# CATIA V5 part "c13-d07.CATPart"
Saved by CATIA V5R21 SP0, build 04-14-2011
Part number: Part1
Bounding box of the stored display mesh (mm): x -49.812 to 35, y -44.222 to 44.222, z 0 to 30
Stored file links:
  D:\CATIA V5R21 E-RESOURCES\CATIA-V5R21\catia-v5r21-Prts\c13_catia_v5r21_prt\c13_catia_v5r21_figr_13-24 & 25\c13-d07.CATPart
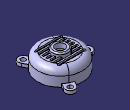
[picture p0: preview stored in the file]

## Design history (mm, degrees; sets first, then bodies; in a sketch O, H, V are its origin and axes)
Body1 (main body)
  Sketch1 on yz-plane, origin (0, 0, 0), H (0, 1, 0), V (0, 0, 1)
    line L1 (0, 0) -> (35, 0)
    line L2 (35, 0) -> (35, 15)
    arc A1 centre (25, 15) radius 10 from (35, 15) to (25, 25) ccw
    line L3 (25, 25) -> (0, 25)
    point P5 (0, 25)
    line L4 (0, 25) -> (0, 0)
    axis line L5 (0, 70.1891) -> (0, -36.6898)
    point P6 (0, 70.1891)
    "Radius" L2 L5 = 35
    distance L1 L3 = 25
    radius A1 = 10
    horizontal: L1 H
    vertical: L2 V, L4 V, L5 V
    tangency: A1 L2, L3 A1
    coincidence: P5 V, P6 V
  Shaft1: profile Sketch1, axis Sketch1.L5, angle 360
  Shell1: ExtOffset 0, Face face of Shaft1, IntOffset 2.5
  Sketch2 on face of Shaft1, origin (0, 0, 0), H (1, 0, 0), V (0, -1, 0)
    projected circle E1 centre (0, 0) radius 35 from edge [face of Shaft1 | face of Shaft1]
    projected arc E2 centre (0, 0) radius 35 from (-34.187, 7.5) to (-34.187, -7.5) ccw from edge [face of Shaft1 | face of Shaft1]
    point P1 (-34.187, 7.5)
    line L1 (-34.187, 7.5) -> (-42.5, 7.5)
    arc A1 centre (-42.5, 0) radius 7.5 from (-42.5, 7.5) to (-42.5, -7.5) ccw
    point P3 (-42.5, 0)
    line L2 (-42.5, -7.5) -> (-34.187, -7.5)
    point P5 (-34.187, -7.5)
    circle A2 centre (-42.5, 0) radius 3.75
    distance P3 V = 42.5
    radius A1 = 7.5
    radius A2 = 3.75
    coincidence: P1 E1, P5 E1, P3 H
    horizontal: L1 H, L2 H
    tangency: A1 L1, L2 A1
  Pad1: profile Sketch2, direction (0, 0, 1), length 5
  CircPattern1: of Pad1, instances 3, angular step 120 {= 360.0*1 deg/CircPattern1.AngularNumber}, axis from face of Shaft1
  Sketch3 on face of Shaft1, origin (0, 0, 25), H (1, 0, 0), V (0, 1, 0)
    construction line L1 (-20, -18) -> (20, -18)
    point P2 (20, -18)
    line L2 (-20, -16.25) -> (20, -16.25)
    line L3 (20, -19.75) -> (-20, -19.75)
    arc A1 centre (20, -18) radius 1.75 from (20, -16.25) to (20, -19.75) cw
    arc A2 centre (-20, -18) radius 1.75 from (-20, -19.75) to (-20, -16.25) cw
    length L1 = 40
    distance H L1 = 18
    distance P2 V = 20
    distance L3 L2 = 3.5
    horizontal: L1 H
    tangency: A1 L2, A2 L2, A1 L3, A2 L3
    parallelism: L1 L2
  Pocket1: profile Sketch3, direction (0, 0, -1), through (limit type 3)
  RectPattern1: of Pocket1, direction 1 instances 7, spacing 6, along yz-plane
  Sketch4 on yz-plane, origin (0, 0, 0), H (0, 1, 0), V (0, 0, 1)
    axis line L1 (0, 0) -> (0, 35.5018)
    point P2 (0, 22.5)
    line L2 (0, 22.5) -> (12.5, 22.5)
    line L3 (12.5, 22.5) -> (12.5, 28)
    arc A1 centre (10.5, 28) radius 2 from (12.5, 28) to (10.5, 30) ccw
    line L4 (10.5, 30) -> (0, 30)
    point P7 (0, 30)
    line L5 (0, 30) -> (0, 22.5)
    reference intersected line E1 (25, 22.5) -> (-25, 22.5) from face of Shell1
    "Radius" L3 L1 = 12.5
    distance L4 L2 = 7.5
    radius A1 = 2
    vertical: L1 V, L3 V, L5 V
    coincidence: P2 L1, P7 L1, L2 E1
    horizontal: L2 H, L4 H
    tangency: A1 L3, L4 A1
  Shaft2: profile Sketch4, axis Sketch4.L1, angle 360
  Sketch5 on face of Shaft2, origin (0, 0, 30), H (1, 0, 0), V (0, 1, 0)
    point P1 (0, 0)
    reference projected circle E1 centre (0, 0) radius 12.5 from edge [face of Shaft2 | face of Shaft2]
    concentricity: P1 E1
  Hole1: placed by Sketch5, at (0, 0, 30) direction (0, 0, -1), diameter 15, through (limit type 3)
